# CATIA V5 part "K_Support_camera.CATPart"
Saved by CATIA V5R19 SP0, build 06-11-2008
Part number: Support_camera
Publications: "Depth_pocket"
Bounding box of the stored display mesh (mm): x -75 to 75, y -69.317 to 74.989, z 0 to 33.723
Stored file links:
  G:\Khaled_CFAO_2011\SIL\SIL_GR2\ctanaphiko\Khaled\CAD_ThinkMOTION\K_Support_camera.CATPart
  G:\Khaled_CFAO_2011\SIL\SIL_GR2\ctanaphiko\CATIA\Conception_Tripod.CATProduct
  G:\Khaled_CFAO_2011\SIL\SIL_GR2\ctanaphiko\CATIA\Squelette.CATPart
  D:\DATA\H310824\My Documents\CFAO\Leg.CATPart
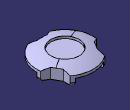
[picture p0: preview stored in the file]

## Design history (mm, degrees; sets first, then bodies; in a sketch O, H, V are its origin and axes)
Parameters
  Depth_pocket = 15 mm
External parameters (linked from other documents)
  External.Width_Leg_Support = 75 mm
  External.Thick_Support = 37.5 mm
  External.Dia_Support = 150 mm
AxisSystem1: origin (0, 0, 0), X (1, 0, 0), Y (0, 1, 0), Z (0, 0, 1)
Set1
  Plane1 "Plan_Ref": linked copy from another document
  DatumPoint1: linked copy from another document
  Plane2 "Plan_Ref": linked copy from another document
Body1 (main body)
Body2
  Sketch1 on Plane2, origin (0, 0, 0), H (1, 0, 0), V (0, 1, 0)
    arc A1 centre (0, 0) radius 75 from (28.6379, -69.3172) to (74.3494, 9.8575) ccw
    line L1 (-28.6379, -69.3172) -> (-12.5, -60)
    line L2 (-12.5, -60) -> (12.5, -60)
    point P2 (12.5, -60)
    line L3 (12.5, -60) -> (28.6379, -69.3172)
    point P6 (58.2115, 19.1747)
    line L4 (74.3494, 9.8575) -> (58.2115, 19.1747)
    line L5 (58.2115, 19.1747) -> (45.7115, 40.8253)
    line L6 (45.7115, 40.8253) -> (45.7115, 59.4597)
    line L7 (-45.7115, 59.4597) -> (-45.7115, 40.8253)
    point P11 (-58.2115, 19.1747)
    line L8 (-45.7115, 40.8253) -> (-58.2115, 19.1747)
    line L9 (-58.2115, 19.1747) -> (-74.3494, 9.8575)
    arc A2 centre (0, 0) radius 75 from (45.7115, 59.4597) to (-45.7115, 59.4597) ccw
    arc A3 centre (0, 0) radius 75 from (-74.3494, 9.8575) to (-28.6379, -69.3172) ccw
    construction line L10 (0, 0) -> (64.9519, 37.5)
    point P13 (64.9519, 37.5)
    construction line L11 (0, 0) -> (-64.9519, 37.5)
    point P14 (-64.9519, 37.5)
    point P15 (80.7587, -46.626)
    radius A1 = 75 {= External.Dia_Support /2}
    length L2 = 25 {= Sketch1.radius(A1) /3}
    distance P2 V = 12.5 {= Sketch1.length(L2) /2}
    distance H L2 = 60 {= Sketch1.radius(A1) *4/5}
    angle L2 L1 = 150
    angle L4 L5 = 150
    angle L5 L2 = 60
    angle L5 L6 = 150
    length L5 = 25 {= Sketch1.length(L2)}
    angle L10 V = 60
    distance P6 L10 = 12.5 {= Sketch1.length(L5) /2}
    angle L11 V = 60
    angle L8 L2 = 60
    length L8 = 25 {= Sketch1.length(L2)}
    distance P11 L11 = 12.5 {= Sketch1.length(L8) /2}
    angle L9 L8 = 150
    angle L7 L8 = 150
    distance O L5 = 60 {= Sketch1.distance(H L2)}
    distance O L8 = 60 {= Sketch1.distance(H L2)}
    radius A3 = 75 {= Sketch1.radius(A1)}
    radius A2 = 75 {= Sketch1.radius(A1)}
    angle L3 L2 = 150
    coincidence: P13 A1, P14 A1, P15 L11
  Pad1: profile Sketch1, direction (0, 0, 1), length 37.5 {= External.Thick_Support}
  Sketch2 on Plane2, origin (0, 0, 0), H (1, 0, 0), V (0, 1, 0)
    line L1 (-37.5, 87.5) -> (-37.5, 50)
    line L2 (-37.5, 50) -> (37.5, 50)
    line L3 (37.5, 50) -> (37.5, 87.5)
    line L4 (-37.5, 87.5) -> (37.5, 87.5)
    length L2 = 75 {= External.Width_Leg_Support}
    distance L2 H = 50 {= External.Dia_Support *1/3}
    length L1 = 37.5 {= Sketch2.length(L2) /2}
    length L3 = 37.5 {= Sketch2.length(L1)}
    distance L3 V = 37.5 {= Sketch2.length(L2) /2}
    vertical: L1 V, L3 V
    horizontal: L2 H
  Pocket1: profile Sketch2, direction (0, 0, 1), length 15 {= Depth_pocket}
  Sketch3 on face of Pocket1 from Sketch2.L3, origin (37.5, 54.4437, 5.7418), H (0, 1, 0), V (0, 0, -1)
    point P1 (3.0322, 0.7418)
    reference projected line E1 (10.5082, 5.7418) -> (10.5082, -9.2582) from edge [face of Pocket1 from Sketch2.L3 | face of Pad1 from Sketch1.A2]
    reference projected line E2 (-16.9437, 5.7418) -> (10.5082, 5.7418) from edge [face of Pocket1 from Sketch2.L3 | start face of Pad1]
    reference projected line E3 (-4.4437, 5.7418) -> (-4.4437, -9.2582) from edge [face of Pocket1 from Sketch2.L3 | face of Pocket1 from Sketch2.L2]
    distance P1 E1 = 7.476 {= Sketch3.distance(E3 E1) /2}
    distance P1 E2 = 5 {= (External.Width_Leg_Support  /30-1mm)*2+2mm}
    distance E3 E1 = 14.9519 (reference)
  Hole1: placed by Sketch3, at (37.5, 57.476, 5) direction (1, 0, 0), diameter 3 {= (External.Width_Leg_Support /30-1mm)*2}, depth 2
  Sketch4 on face of Pocket1 from Sketch2.L1, origin (-37.5, 50.3881, 7.0422), H (0, 1, 0), V (0, 0, 1)
    point P1 (7.0878, -2.0422)
    reference projected line E1 (14.5638, -7.0422) -> (14.5638, 7.9578) from edge [face of Pad1 from Sketch1.A2 | face of Pocket1 from Sketch2.L1]
    reference projected line E2 (14.5638, -7.0422) -> (-12.8881, -7.0422) from edge [face of Pocket1 from Sketch2.L1 | start face of Pad1]
    reference projected line E3 (-0.3881, -7.0422) -> (-0.3881, 7.9578) from edge [face of Pocket1 from Sketch2.L2 | face of Pocket1 from Sketch2.L1]
    reference projected line E4 (14.5638, -7.0422) -> (14.5638, 7.9578) from edge [face of Pad1 from Sketch1.A2 | face of Pocket1 from Sketch2.L1]
    distance P1 E1 = 7.476 {= Sketch4.distance(E3 E4) /2}
    distance P1 E2 = 5 {= (External.Width_Leg_Support /30-1mm)*2+2mm}
    distance E3 E4 = 14.9519 (reference)
  Hole2: placed by Sketch4, at (-37.5, 57.476, 5) direction (-1, 0, 0), diameter 3 {= (External.Width_Leg_Support /30-1mm)*2}, depth 2
  CircPattern1: of Pocket1, instances 3, angular step 120, axis from Z axis
  Sketch5 on face of CircPattern1, origin (-61.3282, 7.8934, 11.1782), H (0.866, 0.5, 0), V (0, 0, 1)
    point P1 (-8.3109, -6.1782)
    reference projected line E1 (-15.7869, -11.1782) -> (-15.7869, 3.8218) from edge [face of CircPattern1 | face of Pad1 from Sketch1.A3]
    reference projected line E2 (11.665, -11.1782) -> (-15.7869, -11.1782) from edge [face of CircPattern1 | start face of Pad1]
    reference projected line E3 (-0.835, -11.1782) -> (-0.835, 3.8218) from edge [face of CircPattern1 | face of CircPattern1]
    reference projected line E4 (-15.7869, -11.1782) -> (-15.7869, 3.8218) from edge [face of CircPattern1 | face of Pad1 from Sketch1.A3]
    distance P1 E1 = 7.476 {= Sketch5.distance(E3 E4) /2}
    distance P1 E2 = 5 {= (External.Width_Leg_Support  /30-1mm)*2+2mm}
    distance E3 E4 = 14.9519 (reference)
  Hole3: placed by Sketch5, at (-68.5256, 3.738, 5) direction (-0.5, 0.866, 0), diameter 3 {= (External.Width_Leg_Support  /30-1mm)*2}, depth 2
  Sketch6 on face of CircPattern1, origin (-24.8593, -57.6538, 7.0245), H (0.866, 0.5, 0), V (0, 0, -1)
    point P1 (-7.1203, 2.0245)
    reference projected line E1 (-14.5963, 7.0245) -> (12.8556, 7.0245) from edge [face of CircPattern1 | start face of Pad1]
    reference projected line E2 (-14.5963, 7.0245) -> (-14.5963, -7.9755) from edge [face of Pad1 from Sketch1.A3 | face of CircPattern1]
    reference projected line E3 (0.3556, 7.0245) -> (0.3556, -7.9755) from edge [face of CircPattern1 | face of CircPattern1]
    reference projected line E4 (-14.5963, 7.0245) -> (-14.5963, -7.9755) from edge [face of Pad1 from Sketch1.A3 | face of CircPattern1]
    distance P1 E1 = 5 {= (External.Width_Leg_Support  /30-1mm)*2+2mm}
    distance P1 E2 = 7.476 {= Sketch6.distance(E3 E4) /2}
    distance E3 E4 = 14.9519 (reference)
  Hole4: placed by Sketch6, at (-31.0256, -61.2139, 5) direction (0.5, -0.866, 0), diameter 3 {= (External.Width_Leg_Support  /30-1mm)*2}, depth 2
  Sketch7 on face of CircPattern1, origin (26.7799, -58.7626, 9.1819), H (0.866, -0.5, 0), V (0, 0, -1)
    point P1 (4.9026, 4.1819)
    reference projected line E1 (12.3785, 9.1819) -> (12.3785, -5.8181) from edge [face of CircPattern1 | face of Pad1 from Sketch1.A1]
    reference projected line E2 (-15.0734, 9.1819) -> (12.3785, 9.1819) from edge [face of CircPattern1 | start face of Pad1]
    reference projected line E3 (-2.5734, 9.1819) -> (-2.5734, -5.8181) from edge [face of CircPattern1 | face of CircPattern1]
    reference projected line E4 (12.3785, 9.1819) -> (12.3785, -5.8181) from edge [face of CircPattern1 | face of Pad1 from Sketch1.A1]
    distance P1 E1 = 7.476 {= Sketch7.distance(E3 E4) /2}
    distance P1 E2 = 5 {= (External.Width_Leg_Support  /30-1mm)*2+2mm}
    distance E3 E4 = 14.9519 (reference)
  Hole5: placed by Sketch7, at (31.0256, -61.2139, 5) direction (-0.5, -0.866, 0), diameter 3 {= (External.Width_Leg_Support  /30-1mm)*2}, depth 2
  Sketch8 on face of CircPattern1, origin (63.5402, 6.6163, 7.7695), H (0.866, -0.5, 0), V (0, 0, 1)
    point P1 (5.7567, -2.7695)
    reference projected line E1 (13.2327, -7.7695) -> (13.2327, 7.2305) from edge [face of Pad1 from Sketch1.A1 | face of CircPattern1]
    reference projected line E2 (13.2327, -7.7695) -> (-14.2192, -7.7695) from edge [face of CircPattern1 | start face of Pad1]
    reference projected line E3 (-1.7192, -7.7695) -> (-1.7192, 7.2305) from edge [face of CircPattern1 | face of CircPattern1]
    reference projected line E4 (13.2327, -7.7695) -> (13.2327, 7.2305) from edge [face of Pad1 from Sketch1.A1 | face of CircPattern1]
    distance P1 E1 = 7.476 {= Sketch8.distance(E3 E4) /2}
    distance P1 E2 = 5 {= (External.Width_Leg_Support   /30-1mm)*2+2mm}
    distance E3 E4 = 14.9519 (reference)
  Hole6: placed by Sketch8, at (68.5256, 3.738, 5) direction (0.5, 0.866, 0), diameter 3 {= (External.Width_Leg_Support  /30-1mm)*2}, depth 2
  Sketch9 on zx-plane, origin (0, 0, 0), H (-1, 0, 0), V (0, 0, 1)
    arc A1 centre (0, -150) radius 187.5 from (0, 37.5) to (-151.3438, -39.3144) ccw
    point P1 (0, -150)
    point P2 (0, 37.5)
    reference projected line E1 (37.5, 0) -> (-37.5, 0) from edge [face of Pocket1 from Sketch2.L2 | start face of Pad1]
    radius A1 = 187.5 {= External.Width_Leg_Support *2.5}
    distance E1 P2 = 37.5 {= External.Thick_Support}
    coincidence: P2 V, P1 V
  Revol1: Element1 Sketch9, Line Z axis, Angle1 360
  Split1: SplitPlane Revol1
  Sketch10 on {plane type Tangent, Support face of Split1, RefPoint {point type OnSurface, Support face of Split1, RefPoint {point stored without definition}, Length 0, Direction (0, 998.2534, -59.0782)}}, origin (-6.868, 12.5718, 36.9575), H (0.9992, 0.0024, 0.0402), V (-0.0005, -0.9973, 0.0738)
    point P1 (6.8536, 12.5739)
    reference projected point E1 (6.8536, 12.5739) from Sketch9.P2
    coincidence: E1 P1
  Hole7: placed by Sketch10, at (-0.0266, 0.0488, 37.5) direction (0.0001, -0.0003, -1), diameter 75 {= External.Width_Leg_Support}, depth 10
  Fillet1: radius 5, on edge [start face of Pad1 | face of Pad1 from Sketch1.A1] (x2); edge [start face of Pad1 | face of Pad1 from Sketch1.A2] (x2); edge [start face of Pad1 | face of Pad1 from Sketch1.A3] (x2)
